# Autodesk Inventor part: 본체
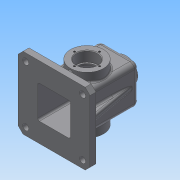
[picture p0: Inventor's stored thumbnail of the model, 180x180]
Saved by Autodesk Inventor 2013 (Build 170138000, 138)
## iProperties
Created: 2018-10
Part Number: 본체
Material: 일반
Document SubType Name: Modeling
Designer: Administrator
Density: 1 g/cm^3
Author: Administrator
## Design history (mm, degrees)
sketch "스케치1"
  geometry: L1 (32.5, -32.5)-(-32.5, -32.5); L2 (-32.5, -32.5)-(-32.5, 32.5); L3 (-32.5, 32.5)-(32.5, 32.5); L4 (32.5, 32.5)-(32.5, -32.5); L5 (32.5, -32.5)-(-32.5, 32.5); L6 (-32.5, -32.5)-(32.5, 32.5); 1 further point
  constraints: 12 end point, 2 midpoint, 2 parallel, 1 horizontal, 1 perpendicular
  dimensions: "d0" = 65 distance of L2.end L3.end; "d1" = 65 distance of L1.end L2.end
extrude "돌출1" new body sketch "스케치1" stored distance "d2" = 110; taper "d3" = 0 deg
sketch "스케치2"
  geometry: L1 (27.5, 27.5)-(-27.5, 27.5); L2 (-27.5, 27.5)-(-27.5, -27.5); L3 (-27.5, -27.5)-(27.5, -27.5); L4 (27.5, -27.5)-(27.5, 27.5); L5 (27.5, 27.5)-(-27.5, -27.5); L6 (-27.5, 27.5)-(27.5, -27.5); 1 further point
  constraints: 12 end point, 2 midpoint, 2 parallel, 1 horizontal, 1 perpendicular
  dimensions: "d4" = 55 distance of L1.start L1.end; "d6" = 55 distance of L3.end L1.start
extrude "돌출2" cut sketch "스케치2" distance "d7" = 105; taper "d8" = 0 deg
sketch "스케치3"
  geometry: L1 (-32.5, -32.5)-(32.5, -32.5) reference; L2 (32.5, -32.5)-(32.5, 32.5) reference; L3 (32.5, 32.5)-(-32.5, 32.5) reference; L4 (-32.5, 32.5)-(-32.5, -32.5) reference; L5 (60, -60)-(-60, -60); L6 (-60, -60)-(-60, 60); L7 (-60, 60)-(60, 60); L8 (60, 60)-(60, -60); L9 (60, -60)-(-60, 60); L10 (-60, -60)-(60, 60); 3 further points
  constraints: 12 end point, 3 midpoint, 2 parallel, 1 coincident, 1 horizontal, 1 perpendicular
  dimensions: "d9" = 120 distance of L6.end L7.end; "d10" = 120 distance of L5.end L6.end
extrude "돌출3" join sketch "스케치3" distance "d11" = 10; taper "d12" = 0 deg
chamfer "모따기1" distance "d13" = 8; stored, may be unused: second distance "d14" = 2, angle "d15" = 45 deg
sketch "스케치4"
  geometry: 5 further points
  constraints: 2 horizontal alignment, 2 vertical alignment
  dimensions: "d16" = 95 distance of point (47.5, 47.5) point (-47.5, 47.5); "d18" = 95 distance of point (-47.5, -47.5) point (-47.5, 47.5); "d19" = 47.5 horizontal distance of point (0, 0) point (-47.5, -47.5); "d20" = 47.5 horizontal distance of point (0, 0) point (-47.5, 47.5)
hole "구멍1" sketch "스케치4" at (-47.5, 47.5), (47.5, 47.5), (47.5, -47.5), (-47.5, -47.5) diameter "d21" = 10; stored, may be unused: countersink angle "d25" = 90 deg, drill point angle "d27" = 118 deg; dims "d22" = 6, "d23" = 4, "d24" = 2, "d26" = 8
fillet "모깎기1" dims "d28" = 3
fillet "모깎기2" dims "d29" = 3
fillet "모깎기3" dims "d30" = 8
fillet "모깎기4" dims "d31" = 8
sketch "스케치5"
  geometry: C1 r 27.5 at (24.5, 45); 1 further point
  constraints: 1 centre point, 1 coincident
  dimensions: "d32" = 55 diameter of C1
extrude "돌출4" join sketch "스케치5" distance "d33" = 15; taper "d34" = 0 deg
sketch "스케치6"
  geometry: C1 r 27.5 at (0, 0) reference; 1 further point
  constraints: 1 vertical alignment
  dimensions: "d35" = 21 distance of C1.centre point (0, 21)
hole "구멍2" sketch "스케치6" at (0, 21) diameter "d36" = 3.242; stored, may be unused: countersink angle "d40" = 90 deg, drill point angle "d42" = 118 deg; dims "d37" = 8, "d38" = 4, "d39" = 2, "d41" = 10
hole "구멍3" diameter "d48" = 30; stored, may be unused: countersink angle "d52" = 90 deg, drill point angle "d54" = 0 deg; dims "d46" = 10, "d47" = 10, "d49" = 8, "d50" = 35, "d51" = 17, "d53" = 10
chamfer "모따기2" distance "d55" = 1; stored, may be unused: second distance "d56" = 2, angle "d57" = 45 deg
fillet "모깎기5" dims "d58" = 3
node "작업 평면1"
sketch "스케치8"
  geometry: 1 further point
sketch "스케치9"
  geometry: C1 r 20 at (0, 0); 1 further point
  constraints: 1 centre point, 1 coincident
  dimensions: "d60" = 40 diameter of C1
extrude "돌출5" join sketch "스케치9" stored distance "d61" = 15; taper "d62" = 7 deg
hole "구멍4" sketch "스케치8" diameter "d63" = 22.835; stored, may be unused: countersink angle "d67" = 90 deg, drill point angle "d69" = 0 deg; dims "d64" = 8, "d65" = 35, "d66" = 17, "d68" = 10
fillet "모깎기6" dims "d70" = 0.3
fillet "모깎기7" dims "d71" = 0.3
sketch "스케치10"
  geometry: L1 (-33, 42.5)-(-42, 42.5); L2 (47, 27.5)-(-55, 27.5) reference; 1 further point
  constraints: 2 end point, 1 horizontal
  dimensions: "d72" = 15 distance between parallel lines of L2 L1
feature "리브1" sketch "스케치10" dims "d73" = 1, "d74" = 6, "d75" = 0, "d76" = 0, "d77" = 1, "d78" = 1
fillet "모깎기8" dims "d79" = 3
fillet "모깎기9" dims "d80" = 3
sketch "스케치11"
  geometry: L1 (-48, -45)-(-43.063, -17); L2 (-60, -55)-(-60, -45) reference; L3 (-52.5, -45)-(-42.5, -45) reference; 1 further point
  constraints: 2 end point, 1 point on line
  dimensions: "d81" = 10 deg angle of L2 L1; "d82" = 12 distance from line of L2 L1.start
feature "리브2" sketch "스케치11" dims "d83" = 1, "d84" = 10, "d85" = 0, "d86" = 0, "d87" = 1, "d88" = 1
fillet "모깎기10" dims "d89" = 3
fillet "모깎기11" dims "d90" = 3
fillet "모깎기12" dims "d91" = 1
sketch "스케치12"
  geometry: L1 (4.5, 18)-(44.5, 18) reference; L2 (-8, 0)-(-8, -91) reference; 1 further point
  constraints: 1 other
  dimensions: "d92" = 26 distance from line of L1 point (24.5, -8); "d93" = 32.5 distance from line of L2 point (24.5, -8)
feature "엠보싱1" sketch "스케치12" dims "d94" = 0.5, "d95" = 0
fillet "모깎기13" dims "d96" = 3
node "솔리드1"
pattern_circular "원형 패턴1" dims angle "d44" = 360 deg
mirror "대칭1"
mirror "대칭2"
mirror "대칭3"
